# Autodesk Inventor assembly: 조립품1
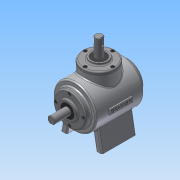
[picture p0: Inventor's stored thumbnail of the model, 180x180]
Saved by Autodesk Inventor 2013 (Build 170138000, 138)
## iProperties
Created: 2015-01
Part Number: 조립품1
Document SubType Name: Assembly
Designer: Administrator
Author: Administrator
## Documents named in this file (15)
- C:\Users\Administrator\Desktop\450106V1019\조립품1.iam
- C:\Users\Administrator\Desktop\450106V1019\본체.ipt
- C:\Users\Administrator\Desktop\450106V1019\M4.ipt
- C:\Users\Administrator\Desktop\450106V1019\메인 베벨기어.ipt
- C:\Users\Administrator\Desktop\450106V1019\메인 축.ipt
- 메인 축.ipt
- C:\Users\Administrator\Desktop\450106V1019\베어링 6203.ipt
- C:\Users\Administrator\Desktop\450106V1019\서브 베벨기어.ipt
- C:\Users\Administrator\Desktop\450106V1019\서브 축.ipt
- 서브 축.ipt
- C:\Users\Administrator\Desktop\450106V1019\오일실.ipt
- C:\Users\Administrator\Desktop\450106V1019\커버.ipt
- C:\Users\Administrator\Desktop\450106V1019\커버2.ipt
- C:\Users\Administrator\Desktop\450106V1019\키 4x4.ipt
- C:\Users\Administrator\Desktop\450106V1019\키 5x5.ipt
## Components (9 placed, 1 different names)
1. M4:3
2. M4:2
3. M4:4
4. M4:5
5. M4:6
6. M4:1
7. M4:7
8. M4:8
9. M4:9
